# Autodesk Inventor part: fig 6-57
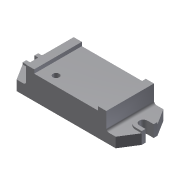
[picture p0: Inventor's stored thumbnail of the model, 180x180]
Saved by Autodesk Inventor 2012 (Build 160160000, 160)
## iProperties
Shininess: 77.0
Angle Display Precision: 2
Document Length Units: 11269
Document Angle Units: 11279
Document Time Units: 11290
Document Mass Units: 11283
Document Length Units Precision: 3
Document Angle Units Precision: 2
Created: 2001-12
Part Number: fig 6-57
Document SubType Name: Modeling
Designer: Renu Muthoo
Density: 1 g/cm^3
Material: Default
Density: 0.0
Volumn: 0.0
Area: 0.0
PropertySet Name: Model Information
Control State: 0
Master: False
Checked Out: False
Author: Renu Muthoo
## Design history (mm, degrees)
sketch "Sketch3"
  geometry: L1 (-59.119, -24.322)-(-59.119, 19.678); L2 (-59.119, 19.678)-(-46.119, 19.678); L3 (-46.119, 19.678)-(-46.119, 13.678); L4 (-46.119, 13.678)-(55.881, 13.678); L5 (55.881, 13.678)-(55.881, 19.678); L6 (55.881, 19.678)-(68.881, 19.678); L7 (68.881, 19.678)-(68.881, -24.322); L8 (68.881, -24.322)-(-59.119, -24.322)
  constraints: 16 end point, 2 equal length
  dimensions: "d10" = 13 distance of L1.end L2.end; "d11" = 102 distance of L3.end L4.end; "d13" = 44 distance between parallel lines of L2 L8; "d14" = 6 distance of L2.end L3.end
extrude "Extrusion1" new body sketch "Sketch3" distance "d15" = 76; taper "d16" = 0 deg
sketch "Sketch4"
  geometry: L1 (0, 0)-(0, 76) reference; L2 (0, 76)-(-15, 76); L3 (-15, 76)-(-31, 50.5); L4 (-31, 50.5)-(-31, 44.5); L5 (-31, 44.5)-(-21, 44.5); L6 (-21, 31.5)-(-31, 31.5); L7 (-31, 31.5)-(-31, 25.5); L8 (-31, 25.5)-(-15, 0); L9 (-15, 0)-(0, 0); L10 (128, 76)-(0, 76) reference; L11 (0, 0)-(128, 0) reference; A1 r 6.5 centre (-21, 38) between (-21, 31.5) and (-21, 44.5)
  constraints: 16 end point, 4 equal length, 3 collinear, 3 parallel, 2 perpendicular, 2 point on circle, 2 tangent, 1 centre point
  dimensions: "d17" = 13 distance between parallel lines of L6 L5; "d18" = 25 distance of L3.end L7.end; "d19" = 10 distance of L6.start L6.end; "d20" = 15 distance of L8.end L1.start; "d21" = 16 horizontal distance of L7.end L8.end
extrude "Extrusion2" join sketch "Sketch4" distance "d22" = 16; taper "d23" = 0 deg
sketch "Sketch5"
  geometry: L1 (-159, 44.5)-(-159, 50.5) reference; L2 (-149, 44.5)-(-159, 44.5) reference; L3 (-159, 31.5)-(-149, 31.5) reference; L4 (-159, 25.5)-(-159, 31.5) reference; L5 (-159, 25.5)-(-149, 25.5); L6 (-149, 50.5)-(-159, 50.5); A1 r 6.5 centre (-149, 38) between (-149, 31.5) and (-149, 44.5) reference; A2 r 12.5 centre (-149, 38) between (-149, 25.5) and (-149, 50.5)
  constraints: 4 end point, 2 point on circle, 2 tangent, 1 centre point, 1 parallel, 1 perpendicular
extrude "Extrusion3" join sketch "Sketch5" distance "d24" = 19; taper "d25" = 0 deg
workplane "Work Plane1"
mirror "Mirror1"
fillet "Fillet1" dims "d27" = 4
sketch "Sketch6"
  geometry: L1 (0, 0)-(0, 76) reference; L2 (0, 0)-(102, 0) reference; 1 further point
  dimensions: "d28" = 20 distance from line of L1 point (20, 15); "d29" = 15 distance from line of L2 point (20, 15)
hole "Hole1" sketch "Sketch6" at (20, 15) diameter "d30" = 10; stored, may be unused: countersink angle "d34" = 82 deg, drill point angle "d36" = 118 deg; dims "d31" = 6, "d32" = 4, "d33" = 2, "d35" = 15
sketch "Sketch7"
  geometry: C1 r 5 at (20, 15) reference; 3 further points
  constraints: 4 other
body "Solid1"
other parameters: "d26" = -64
